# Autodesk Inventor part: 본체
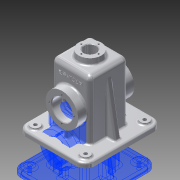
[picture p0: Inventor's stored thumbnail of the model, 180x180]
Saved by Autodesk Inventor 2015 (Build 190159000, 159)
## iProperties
Created: 2016-02
Part Number: 본체
Material: 알루미늄 6061
Document SubType Name: Modeling
Designer: Administrator
Density: 2.7 g/cm^3
Appearance: 알루미늄 - 평지
Mass: 801.79 g
Surface Area: 906.477 cm^2
Volume: 296.959 cm^3
Author: Administrator
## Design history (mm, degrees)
sketch "스케치1"
  geometry: L1 (-42.5, 65)-(42.5, 65); L2 (57.5, 50)-(57.5, -50); L3 (42.5, -65)-(-42.5, -65); L4 (-57.5, -50)-(-57.5, 50); L5 (-57.5, 65)-(57.5, -65); L6 (57.5, 65)-(-57.5, -65); A1 r 15 centre (-42.5, 50) between (-42.5, 65) and (-57.5, 50); A2 r 15 centre (-42.5, -50) between (-57.5, -50) and (-42.5, -65); A3 r 15 centre (42.5, -50) between (42.5, -65) and (57.5, -50); A4 r 15 centre (42.5, 50) between (57.5, 50) and (42.5, 65); 1 further point
  constraints: 12 end point, 8 point on circle, 8 point on line, 8 tangent, 4 centre point, 3 equal radius, 2 midpoint, 2 parallel, 1 horizontal, 1 perpendicular
  dimensions: "d0" = 130 distance of L6.start L5.end; "d1" = 115 distance of L5.start L6.start; "d2" = 15 radius of A1
extrude "돌출1" new body sketch "스케치1" distance "d3" = 10; taper "d4" = 0 deg
sketch "스케치2"
  geometry: C1 r 7.5 at (-42.5, 50); C2 r 7.5 at (42.5, 50); C3 r 7.5 at (42.5, -50); C4 r 7.5 at (-42.5, -50); A1 r 15 centre (-42.5, -50) between (-57.5, -50) and (-42.5, -65) reference; A2 r 15 centre (42.5, -50) between (42.5, -65) and (57.5, -50) reference; A3 r 15 centre (42.5, 50) between (57.5, 50) and (42.5, 65) reference; A4 r 15 centre (-42.5, 50) between (-42.5, 65) and (-57.5, 50) reference; 1 further point
  constraints: 4 centre point, 4 coincident
  dimensions: "d5" = 15 diameter of C1; "d6" = 15 diameter of C2 (= d5); "d7" = 15 diameter of C3 (= d6); "d8" = 15 diameter of C4 (= d5)
extrude "돌출2" join sketch "스케치2" distance "d9" = 3; taper "d10" = 0 deg
sketch "스케치3"
  geometry: L1 (57.5, 50)-(57.5, -50) reference; L2 (-42.5, 65)-(42.5, 65) reference; L3 (-57.5, -50)-(-57.5, 50) reference; L4 (42.5, -65)-(-42.5, -65) reference; L5 (-52.5, -50)-(-52.5, 50); L6 (-42.5, 60)-(42.5, 60); L7 (52.5, 50)-(52.5, -50); L8 (42.5, -60)-(-42.5, -60); L9 (-57.5, -50)-(-57.5, 50); L10 (-42.5, 65)-(42.5, 65); L11 (57.5, 50)-(57.5, -50); L12 (42.5, -65)-(-42.5, -65); A1 r 15 centre (42.5, 50) between (57.5, 50) and (42.5, 65) reference; A2 r 15 centre (-42.5, 50) between (-42.5, 65) and (-57.5, 50) reference; A3 r 15 centre (-42.5, -50) between (-57.5, -50) and (-42.5, -65) reference; A4 r 15 centre (42.5, -50) between (42.5, -65) and (57.5, -50) reference; A5 r 10 centre (-42.5, -50) between (-52.5, -50) and (-42.5, -60); A6 r 10 centre (-42.5, 50) between (-42.5, 60) and (-52.5, 50); A7 r 10 centre (42.5, 50) between (52.5, 50) and (42.5, 60); A8 r 10 centre (42.5, -50) between (42.5, -60) and (52.5, -50); A9 r 15 centre (-42.5, -50) between (-57.5, -50) and (-42.5, -65); A10 r 15 centre (-42.5, 50) between (-42.5, 65) and (-57.5, 50); A11 r 15 centre (42.5, 50) between (57.5, 50) and (42.5, 65); A12 r 15 centre (42.5, -50) between (42.5, -65) and (57.5, -50); 1 further point
  constraints: 16 end point, 16 point on circle, 8 centre point, 14 other
  dimensions: "d11" = 5 distance between parallel lines of L4 L8; "d12" = 0 distance between parallel lines of L4 L12
extrude "돌출3" cut sketch "스케치3" distance "d13" = 2; taper "d14" = 0 deg
sketch "스케치5"
  geometry: L1 (-42.5, 0)-(42.5, 0) reference; C1 r 27.5 at (0, 55); C2 r 15 at (0, 55); 2 further points
  constraints: 2 centre point, 1 coincident, 1 midpoint, 1 vertical alignment
  dimensions: "d17" = 55 diameter of C1; "d18" = 55 distance from line of L1 C1.centre; "d19" = 30 diameter of C2
extrude "돌출4" join sketch "스케치5" stored distance "d20" = 95; taper "d21" = 0 deg
sketch "스케치6"
  geometry: L1 (-24.5, 32.5)-(24.5, 32.5); L2 (32.5, 24.5)-(32.5, -24.5); L3 (24.5, -32.5)-(-24.5, -32.5); L4 (-32.5, -24.5)-(-32.5, 24.5); L5 (-32.5, 32.5)-(32.5, -32.5); L6 (32.5, 32.5)-(-32.5, -32.5); A1 r 8 centre (-24.5, 24.5) between (-24.5, 32.5) and (-32.5, 24.5); A2 r 8 centre (-24.5, -24.5) between (-32.5, -24.5) and (-24.5, -32.5); A3 r 8 centre (24.5, -24.5) between (24.5, -32.5) and (32.5, -24.5); A4 r 8 centre (24.5, 24.5) between (32.5, 24.5) and (24.5, 32.5); 3 further points
  constraints: 12 end point, 8 point on circle, 8 point on line, 8 tangent, 4 centre point, 4 midpoint, 3 equal radius, 2 parallel, 1 horizontal, 1 perpendicular
  dimensions: "d22" = 65 distance of L6.start L5.end; "d23" = 65 distance of L5.start L6.start; "d47" = 8 radius of A1
extrude "돌출5" join sketch "스케치6" distance "d28" = 100; taper "d29" = 0 deg
sketch "스케치7"
  geometry: L1 (24.5, -32.5)-(-24.5, -32.5) reference; L2 (-24.5, 32.5)-(24.5, 32.5) reference; L3 (-3, -22.5)-(3, -22.5); L4 (3, -22.5)-(3, -42.5); L5 (3, -42.5)-(-3, -42.5); L6 (-3, -42.5)-(-3, -22.5); L7 (-3, -22.5)-(3, -42.5); L8 (3, -22.5)-(-3, -42.5); L9 (-3, 42.5)-(3, 42.5); L10 (3, 42.5)-(3, 22.5); L11 (3, 22.5)-(-3, 22.5); L12 (-3, 22.5)-(-3, 42.5); L13 (-3, 42.5)-(3, 22.5); L14 (3, 42.5)-(-3, 22.5); 7 further points
  constraints: 24 end point, 6 midpoint, 4 parallel, 2 horizontal, 2 perpendicular
  dimensions: "d30" = 10 distance between parallel lines of L5 L1; "d31" = 6 distance of L4.end L5.end; "d32" = 10 distance between parallel lines of L2 L9; "d33" = 6 distance of L9.start L9.end
extrude "돌출6" join sketch "스케치7" stored distance "d34" = 100; taper "d35" = 0 deg
sketch "스케치9"
  geometry: C1 r 20 at (0, 0); 1 further point
  constraints: 1 centre point, 1 coincident
  dimensions: "d37" = 40 diameter of C1
extrude "돌출7" join sketch "스케치9" distance "d38" = 10; taper "d39" = -5 deg
sketch "스케치11"
  geometry: L1 (27.5, -27.5)-(-27.5, -27.5); L2 (-27.5, -27.5)-(-27.5, 27.5); L3 (-27.5, 27.5)-(27.5, 27.5); L4 (27.5, 27.5)-(27.5, -27.5); L5 (27.5, -27.5)-(-27.5, 27.5); L6 (-27.5, -27.5)-(27.5, 27.5); 1 further point
  constraints: 12 end point, 2 midpoint, 2 parallel, 1 horizontal, 1 perpendicular
  dimensions: "d40" = 55 distance of L1.start L1.end; "d41" = 55 distance of L1.end L2.end
extrude "돌출8" cut sketch "스케치11" distance "d42" = 105; taper "d43" = 0 deg
sketch "스케치12"
  geometry: C1 r 19.125 at (0, 0) reference; C2 r 10.5 at (0, 0)
  constraints: 1 centre point, 1 coincident
  dimensions: "d44" = 21 diameter of C2
extrude "돌출9" cut sketch "스케치12" stored distance "d45" = 105; taper "d46" = 0 deg
sketch "스케치14"
  geometry: L1 (-32.5, 10)-(-32.5, 110) reference; L2 (-32.5, 95.069)-(-47.5, 10); L3 (-47.5, 10)-(-32.5, 10); L4 (-50, 10)-(-35, 10) reference; L5 (-32.5, 10)-(-32.5, 95.069); L6 (-57.5, 2)-(-57.5, 10) reference; L7 (32.5, 10)-(32.5, 110) reference; L8 (32.5, 95.069)-(32.5, 10); L9 (32.5, 10)-(47.5, 10); L10 (35, 10)-(50, 10) reference; L11 (47.5, 10)-(32.5, 95.069); L12 (57.5, 2)-(57.5, 10) reference; 1 further point
  constraints: 12 end point, 3 collinear, 3 point on line
  dimensions: "d51" = 10 distance from line of L6 L2.end; "d52" = 10 deg angle of L6 L2; "d53" = 10 distance from line of L9.end L12; "d54" = 10 deg angle of L12 L11
extrude "돌출10" join sketch "스케치14" stored distance "d55" = 10; taper "d56" = 0 deg
sketch "스케치15"
  geometry: C1 r 15 at (0, 0) reference; C2 r 15 at (0, 0); 1 further point
  constraints: 1 centre point, 1 coincident, 1 concentric
extrude "돌출11" cut sketch "스케치15" stored distance "d57" = 6; taper "d58" = 0 deg
sketch "스케치16"
  geometry: C1 r 15 at (0, 0) reference; C2 r 27.5 at (0, 0) reference; C3 r 17.5 at (0, 0); 1 further point
  constraints: 1 centre point, 1 coincident
  dimensions: "d59" = 35 diameter of C3
extrude "돌출12" cut sketch "스케치16" distance "d60" = 17; taper "d61" = 0 deg
sketch "스케치17"
  geometry: C1 r 15 at (0, 0) reference; C2 r 27.5 at (0, 0) reference; C3 r 17.5 at (0, 0); 1 further point
  constraints: 1 centre point, 1 coincident
  dimensions: "d62" = 35 diameter of C3
extrude "돌출13" cut sketch "스케치17" distance "d63" = 17; taper "d64" = 0 deg
fillet "모깎기1" dims "d65" = 3
fillet "모깎기2" dims "d66" = 3
fillet "모깎기3" dims "d67" = 3
fillet "모깎기4" dims "d68" = 3
fillet "모깎기5" dims "d69" = 3
fillet "모깎기6" dims "d70" = 3
chamfer "모따기1" distance "d71" = 1; stored, may be unused: second distance "d72" = 2, angle "d73" = 45 deg
fillet "모깎기7" dims "d74" = 3
fillet "모깎기8" dims "d75" = 3
fillet "모깎기9" dims "d76" = 8
fillet "모깎기10" dims "d77" = 3
node "작업 평면1"
sketch "스케치19"
  geometry: L1 (-19.125, 65)-(19.125, 65) reference; 2 further points
  constraints: 1 vertical alignment, 1 other
  dimensions: "d80" = 26 distance from line of L1 point (0, 39)
feature "엠보싱1" sketch "스케치19" dims "d81" = 0.5, "d82" = 0
hole "구멍1" diameter "d85" = 6; stored, may be unused: countersink angle "d89" = 90 deg, drill point angle "d91" = 118 deg; dims "d86" = 6, "d87" = 4, "d88" = 2, "d90" = 8, "d110" = 10, "d111" = 10
hole "구멍2" diameter "d94" = 6; stored, may be unused: countersink angle "d98" = 90 deg, drill point angle "d100" = 118 deg; dims "d95" = 6, "d96" = 4, "d97" = 2, "d99" = 8, "d112" = 10, "d113" = 10
hole "구멍3" diameter "d103" = 6; stored, may be unused: countersink angle "d107" = 90 deg, drill point angle "d109" = 118 deg; dims "d101" = 10, "d102" = 10, "d104" = 6, "d105" = 4, "d106" = 2, "d108" = 8
hole "구멍4" diameter "d116" = 6; stored, may be unused: countersink angle "d120" = 90 deg, drill point angle "d122" = 118 deg; dims "d114" = 10, "d115" = 10, "d117" = 6, "d118" = 4, "d119" = 2, "d121" = 8
sketch "스케치20"
  geometry: C1 r 27.5 at (0, 0) reference; 2 further points
  constraints: 1 vertical alignment
  dimensions: "d123" = 21 distance of C1.centre point (0, 21)
hole "구멍5" sketch "스케치20" at (0, 21) diameter "d124" = 3.242; stored, may be unused: countersink angle "d128" = 90 deg, drill point angle "d130" = 118 deg; dims "d125" = 8, "d126" = 4, "d127" = 2, "d129" = 10
sketch "스케치21"
  geometry: L1 (-42.5, 55)-(42.5, 55) reference; C1 r 27.5 at (0, 0) reference; 3 further points
  constraints: 1 midpoint, 1 vertical alignment
  dimensions: "d134" = 21 distance of C1.centre point (0, -21)
hole "구멍6" sketch "스케치21" at (0, -21) diameter "d135" = 3.242; stored, may be unused: countersink angle "d139" = 90 deg, drill point angle "d141" = 118 deg; dims "d136" = 8, "d137" = 4, "d138" = 2, "d140" = 10
sketch "스케치22"
  geometry: C1 r 19.125 at (0, 0) reference; 1 further point
  constraints: 1 horizontal alignment
  dimensions: "d145" = 14.5 distance of C1.centre point (-14.5, 0)
hole "구멍7" sketch "스케치22" at (-14.5, 0) diameter "d146" = 2.459; stored, may be unused: countersink angle "d150" = 90 deg, drill point angle "d152" = 118 deg; dims "d147" = 7, "d148" = 4, "d149" = 2, "d151" = 9
fillet "모깎기11" dims "d156" = 0.3
fillet "모깎기12" dims "d157" = 3
node "솔리드1"
pattern_circular "원형 패턴1" dims angle "d132" = 360 deg
pattern_circular "원형 패턴2" dims angle "d143" = 360 deg
pattern_circular "원형 패턴3" dims angle "d154" = 360 deg
other parameters: "d79" = 62
